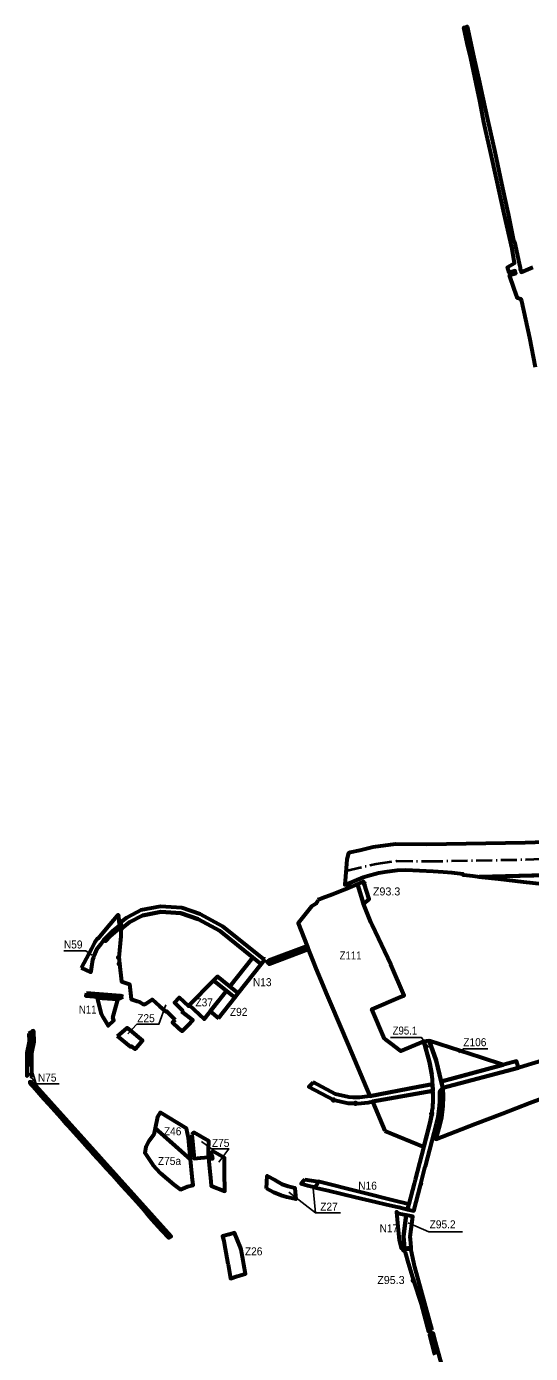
# Model space of a CAD drawing. Extents: x -650277 to -643420, y -1073980 to -1066720.
# Drawn here: x -650277 to -648765, y -1070698 to -1066720 of the extents above; entities that cross this region are included whole.
import ezdxf

# ---------------------------------------------------------------- set-up
doc = ezdxf.new("R2010")
doc.units = 0
doc.header["$LTSCALE"] = 9.6
doc.header["$PDMODE"] = 32
doc.header["$PDSIZE"] = 4.8
doc.linetypes.add('DOT_DASHED', pattern=[7.7, 5, -1.2, 0.3, -1.2])
for name, color, linetype, lineweight in [('1', 7, 'Continuous', 60), ('11', 7, 'Continuous', 60), ('12', 7, 'Continuous', 60), ('13', 7, 'Continuous', 60), ('15', 7, 'Continuous', 60), ('18', 7, 'Continuous', 60), ('24', 7, 'Continuous', 60), ('3', 7, 'Continuous', 60), ('34', 7, 'Continuous', 60), ('40', 7, 'Continuous', 60), ('41', 7, 'Continuous', 60), ('42', 7, 'Continuous', 60), ('48', 7, 'Continuous', 60), ('60', 7, 'Continuous', 60), ('62', 7, 'DOT_DASHED', 40), ('63', 7, 'Continuous', 25), ('7', 7, 'Continuous', 60), ('9', 7, 'Continuous', 60)]:
    doc.layers.add(name, color=color, linetype=linetype, lineweight=lineweight)

msp = doc.modelspace()

# ---------------------------------------------------------------- linework, layer by layer
at = {"layer": '1'}
for points in [[(-650004.59, -1069747.27), (-649974.86, -1069721.96), (-649966.52, -1069728.87), (-649929.38, -1069759.65), (-649951.56, -1069785.42), (-649963, -1069776.7), (-649965, -1069778.7)], [(-649557.21, -1070203.53), (-649555.44, -1070165.91), (-649532.57, -1070178.08), (-649509.72, -1070190.24), (-649492.67, -1070196.34), (-649472.6, -1070201.15), (-649472.43, -1070202.9), (-649469.176, -1070235.365), (-649496, -1070230), (-649513, -1070225), (-649535, -1070216)], [(-649442.63, -1070176.69), (-649402.29, -1070182.92), (-649404.2, -1070187.43), (-649412.2, -1070200.71), (-649433.3, -1070195.89), (-649453.27, -1070190.02), (-649446.19, -1070180.76)], [(-649678.92, -1070395.81), (-649672.83, -1070429.29), (-649672.49, -1070431.16), (-649664.82, -1070473.32), (-649644.74, -1070466.68), (-649640.18, -1070465.2), (-649624.33, -1070460.03), (-649620.17, -1070459.09), (-649624.97, -1070431.24), (-649627.13, -1070419.17), (-649633, -1070386.46), (-649635.52, -1070380.14), (-649653.03, -1070336.2), (-649669.24, -1070341.04), (-649670.28, -1070341.35), (-649689.02, -1070346.94), (-649685.31, -1070360.88), (-649683.08, -1070373.11)]]:
    msp.add_lwpolyline(points, close=True, dxfattribs=at)
at = {"layer": '11'}
msp.add_lwpolyline([(-649788.91, -1069654.4), (-649744.517, -1069695.746), (-649677.124, -1069610.681), (-649715.908, -1069579.804)], close=True, dxfattribs=at)
at = {"layer": '12'}
for points in [[(-649891.21, -1070022.68), (-649832.007, -1070074.751), (-649784.87, -1070116.76), (-649791.31, -1070051.51), (-649797.45, -1070023.77), (-649876.31, -1069975.93), (-649884.59, -1069988.57)], [(-649891.21, -1070022.68), (-649895.45, -1070042.15), (-649910.34, -1070061.29), (-649919.55, -1070079.01), (-649922.3, -1070096.9), (-649898.55, -1070132.9), (-649874.94, -1070157.19), (-649835.28, -1070191.27), (-649815.33, -1070206.63), (-649794.37, -1070197.2), (-649777.29, -1070193.57), (-649779.75, -1070168.69), (-649784.87, -1070116.76)]]:
    msp.add_lwpolyline(points, close=True, dxfattribs=at)
at = {"layer": '13'}
msp.add_line((-649202.375, -1070030.469), (-649085.737, -1070078.201), dxfattribs=at)
for points in [[(-649057.868, -1069910.51), (-649239.635, -1069943.094), (-649202.375, -1070030.469)], [(-649085.737, -1070078.201), (-649066.487, -1070004.267), (-649061.139, -1069979.254), (-649061.138, -1069979.243)]]:
    msp.add_lwpolyline(points, dxfattribs=at)
msp.add_arc((-649347.129, -1069931.193), 290, 350.46253, 4.08974, dxfattribs=at)
msp.add_point((-649061.138, -1069979.243), dxfattribs=at)
at = {"layer": '15'}
msp.add_line((-649057.868, -1069910.51), (-649058.82, -1069890.548), dxfattribs=at)
for points in [[(-648749.97, -1067741.49), (-648767.84, -1067652.98), (-648791.68, -1067543.78), (-648792.97, -1067537.86), (-648804.08, -1067534.88), (-648813.94, -1067506.27), (-648827.86, -1067465.86), (-648809.65, -1067459.77), (-648809.97, -1067458.52), (-648811.21, -1067453.52), (-648811.4, -1067452.79), (-648829.54, -1067458.42), (-648834.01, -1067441.81), (-648812.91, -1067429.16), (-648820.39, -1067386.83), (-648844.16, -1067281.37), (-648845.94, -1067272.85), (-648867.82, -1067176.66), (-648884.26, -1067099.63), (-648899.1, -1067033.34), (-648905.06, -1067006.7), (-648917.76, -1066942.65), (-648924.32, -1066909.55), (-648936.7, -1066852.52), (-648944.75, -1066815.41), (-648955.15, -1066770.11), (-648965.39, -1066723.15), (-648959.88, -1066721.59), (-648954.86, -1066720.16), (-648935.19, -1066812.53), (-648918.27, -1066888.41), (-648914.11, -1066907.05), (-648893.02, -1067002.5), (-648872.31, -1067095.5), (-648851.87, -1067191.04), (-648835.29, -1067268.93), (-648833.66, -1067276.77), (-648816.06, -1067361.71), (-648813.81, -1067365.91), (-648799.58, -1067430.4), (-648796.8, -1067443.1), (-648795.88, -1067447.21), (-648794.7, -1067452.46), (-648793.71, -1067456.88), (-648757.97, -1067441.51)], [(-649561.17, -1069515.83), (-649566.951, -1069515.099), (-649688.625, -1069418.156), (-649755.971, -1069381.179), (-649810.846, -1069362.154), (-649875.434, -1069357.751), (-649934.363, -1069369.537), (-649945.397, -1069375.277), (-649977.239, -1069391.714), (-649994.329, -1069405.451)], [(-649994.293, -1069425.949), (-649968.465, -1069405.189), (-649929.015, -1069384.784), (-649874.391, -1069373.859)], [(-649874.391, -1069373.859), (-649814.067, -1069377.972), (-649762.488, -1069395.854), (-649697.525, -1069431.522), (-649598.004, -1069510.814), (-649572.972, -1069530.758)], [(-649994.329, -1069405.451), (-649994.329, -1069405.451), (-649994.293, -1069425.949), (-649994.293, -1069425.949)], [(-649572.972, -1069530.758), (-649561.91, -1069516.78), (-649561.17, -1069515.83)], [(-650096.627, -1069617.746), (-650099.55, -1069625.53), (-650002.39, -1069633.65)], [(-649987.49, -1069628.6), (-649994.913, -1069626.246), (-650096.627, -1069617.746)], [(-650002.39, -1069633.65), (-650002.65, -1069637.14), (-649987.49, -1069628.6)], [(-649417.234, -1069885.193), (-649418.94, -1069887.36), (-649430.515, -1069898.514), (-649356.458, -1069937.945)], [(-649246.81, -1069926.27), (-649278.492, -1069930.573), (-649296.851, -1069931.092), (-649310.738, -1069929.342), (-649350.222, -1069920.873), (-649417.234, -1069885.193)], [(-649058.82, -1069890.548), (-649101.89, -1069898.73), (-649246.81, -1069926.27)], [(-649356.458, -1069937.945), (-649312.646, -1069947.342), (-649289.95, -1069948.146)], [(-649289.95, -1069948.146), (-649282.437, -1069948.342), (-649251.805, -1069945.276), (-649239.635, -1069943.094), (-649057.868, -1069910.51)]]:
    msp.add_lwpolyline(points, dxfattribs=at)
for points in [[(-650025.31, -1069446.49), (-649998.512, -1069422.926), (-649999.01, -1069415.628), (-650018.873, -1069431.749), (-650043.521, -1069455.69), (-650045.72, -1069459.1), (-650040.012, -1069461.999)], [(-649547.733, -1069530.185), (-649431.761, -1069486.57), (-649435.578, -1069476.772), (-649550.53, -1069519.68), (-649554.83, -1069525), (-649551.32, -1069528.49), (-649549.69, -1069530.14), (-649548.881, -1069530.963)], [(-649677.124, -1069610.681), (-649651.846, -1069630.82), (-649641.978, -1069618.226), (-649667.188, -1069598.14), (-649688.446, -1069581.203), (-649704.646, -1069568.296), (-649715.908, -1069579.804)], [(-648800.85, -1069841.52), (-648806.946, -1069821.79), (-649032.928, -1069882.782), (-649028.017, -1069902.109)]]:
    msp.add_lwpolyline(points, close=True, dxfattribs=at)
for p in [(-649994.329, -1069405.451), (-649994.293, -1069425.949), (-649356.458, -1069937.945), (-649289.95, -1069948.146)]:
    msp.add_point(p, dxfattribs=at)
at = {"layer": '18'}
for points in [[(-649781.53, -1070041.2), (-649774.45, -1070113.92), (-649754.82, -1070111.89), (-649731.12, -1070109.96), (-649730.96, -1070094.91), (-649730.89, -1070088.96), (-649730.6, -1070061.98), (-649774.73, -1070035.58)], [(-649730.57, -1070115.76), (-649730, -1070122.01), (-649726.22, -1070162.75), (-649725.49, -1070170.64), (-649723.17, -1070195.81), (-649682.04, -1070211.58), (-649683.12, -1070154.14), (-649682.98, -1070132.1), (-649683.57, -1070112.05), (-649717.72, -1070091.61), (-649718.71, -1070093.35), (-649724.36, -1070099.03), (-649719.69, -1070108.94), (-649719.24, -1070114.87)]]:
    msp.add_lwpolyline(points, close=True, dxfattribs=at)
at = {"layer": '24'}
for points in [[(-649321.69, -1069307.61), (-649324.3, -1069308.59), (-649359.48, -1069321.82), (-649389.4, -1069333.35), (-649396.52, -1069336.09), (-649403.92, -1069338.26)], [(-649283.702, -1069294.132), (-649284.695, -1069291.033), (-649300.133, -1069297.95), (-649321.69, -1069307.61)], [(-649060.897, -1069861.994), (-649068, -1069825.147), (-649085.41, -1069762.44), (-649085.41, -1069762.44), (-649099.75, -1069768.575), (-649154.76, -1069792.11), (-649184.05, -1069768.45), (-649200.64, -1069756.53), (-649202.99, -1069754.99), (-649241.11, -1069665.9), (-649155.082, -1069629.097), (-649144.57, -1069624.6), (-649184.1, -1069532.2), (-649240.202, -1069414.528), (-649244.08, -1069404.753), (-649265.774, -1069350.068), (-649283.702, -1069294.132)], [(-649403.92, -1069338.26), (-649403.03, -1069340.66), (-649408.81, -1069349.89), (-649422.19, -1069357.99), (-649462.25, -1069408.32), (-649435.578, -1069476.772), (-649431.761, -1069486.57)], [(-649431.761, -1069486.57), (-649416.52, -1069525.68), (-649409.355, -1069544.517), (-649388.438, -1069594.296), (-649379.32, -1069615.71), (-649364.44, -1069650.55), (-649312.03, -1069773.33)], [(-649312.03, -1069773.33), (-649246.81, -1069926.27), (-649101.89, -1069898.73), (-649058.82, -1069890.548)]]:
    msp.add_lwpolyline(points, dxfattribs=at)
msp.add_arc((-649649.71, -1069919.176), 591.583, 2.77379, 5.54687, dxfattribs=at)
at = {"layer": '3'}
msp.add_lwpolyline([(-648722.24, -1069817.54), (-648772.48, -1069832.83), (-648800.85, -1069841.52), (-649028.017, -1069902.109), (-649027.135, -1069928.902), (-649027.953, -1069955.702), (-649032.644, -1069990.371), (-649037.411, -1070011.659), (-649048.918, -1070055.852), (-648931.057, -1070010.171), (-648849.532, -1069978.559), (-648767.83, -1069946.87), (-648562.242, -1069870.301)], dxfattribs=at)
at = {"layer": '34'}
msp.add_line((-649032.928, -1069882.782), (-649002.558, -1069874.585), dxfattribs=at)
for points in [[(-649002.558, -1069874.585), (-648846.924, -1069832.58), (-648914.48, -1069810.75), (-649069.4, -1069760.67)], [(-649069.4, -1069760.67), (-649048, -1069820), (-649032.928, -1069882.782)]]:
    msp.add_lwpolyline(points, dxfattribs=at)
at = {"layer": '40'}
for points in [[(-649667.188, -1069598.14), (-649641.978, -1069618.226), (-649572.972, -1069530.758), (-649598.004, -1069510.814)], [(-650002.65, -1069637.14), (-650050.26, -1069633.65), (-650064.77, -1069633.06), (-650052.88, -1069679.49), (-650047.45, -1069690.69), (-650031.64, -1069715.9), (-650015.53, -1069700.21), (-650018.31, -1069690.89), (-650011.15, -1069665.82)], [(-649160.748, -1070243.413), (-649402.29, -1070182.92), (-649404.2, -1070187.43), (-649412.2, -1070200.71), (-649412.2, -1070200.71), (-649408.24, -1070201.62), (-649372.69, -1070209.74), (-649289.83, -1070229.16), (-649229.8, -1070243.94), (-649197.55, -1070251.65), (-649164.91, -1070258.55), (-649160.54, -1070259.96), (-649134.294, -1070266.095), (-649130.712, -1070250.935)]]:
    msp.add_lwpolyline(points, close=True, dxfattribs=at)
at = {"layer": '41'}
msp.add_line((-650000.59, -1069511.15), (-649998.5, -1069529.88), dxfattribs=at)
for points in [[(-649814.067, -1069377.972), (-649874.391, -1069373.859), (-649929.015, -1069384.784), (-649968.465, -1069405.189)], [(-649598.004, -1069510.814), (-649697.525, -1069431.522), (-649762.488, -1069395.854), (-649814.067, -1069377.972)], [(-649968.465, -1069405.189), (-649994.293, -1069425.949), (-649994.53, -1069447.61), (-650000.59, -1069511.15), (-650000.59, -1069511.15)], [(-649998.5, -1069529.88), (-649992.59, -1069582.88), (-649967.81, -1069590.74), (-649962.71, -1069636.458)], [(-649812.153, -1069672.884), (-649809.47, -1069670.13), (-649833.38, -1069646.08), (-649818.71, -1069630.64), (-649791.3, -1069657.21), (-649788.91, -1069654.4), (-649715.908, -1069579.804), (-649704.646, -1069568.296), (-649688.446, -1069581.203), (-649667.188, -1069598.14), (-649598.004, -1069510.814)], [(-649962.71, -1069636.458), (-649962.71, -1069636.46), (-649954.365, -1069639.105), (-649944.963, -1069642.085)], [(-649944.963, -1069642.085), (-649938.2, -1069644.23), (-649924.8, -1069652.19), (-649920.45, -1069649.53), (-649900.64, -1069636.78), (-649877.82, -1069656.83), (-649864.596, -1069668.455), (-649859.96, -1069672.53)], [(-649859.96, -1069672.53), (-649859.17, -1069673.22), (-649857.49, -1069671.46), (-649833.94, -1069695.24), (-649831.124, -1069698.083)], [(-649812.153, -1069672.884), (-649808.96, -1069675.34), (-649777.94, -1069699.2), (-649792.13, -1069713.65), (-649807.66, -1069729.46), (-649810.41, -1069732.28), (-649819.9, -1069723.61), (-649838.99, -1069706.15), (-649831.124, -1069698.083)], [(-649831.124, -1069698.083), (-649838.99, -1069706.15), (-649819.9, -1069723.61), (-649810.41, -1069732.28), (-649807.66, -1069729.46), (-649792.13, -1069713.65), (-649777.94, -1069699.2), (-649808.96, -1069675.34), (-649812.153, -1069672.884)]]:
    msp.add_lwpolyline(points, dxfattribs=at)
for p in [(-650000.59, -1069511.15), (-649998.5, -1069529.88)]:
    msp.add_point(p, dxfattribs=at)
at = {"layer": '42'}
msp.add_lwpolyline([(-650112.18, -1069542.11), (-650081.29, -1069484.35), (-650072.5, -1069466.44), (-650063.12, -1069453.54), (-650062.17, -1069454.05), (-650060.29, -1069451.7), (-650057.49, -1069448.18), (-650026.33, -1069411.47), (-650003.73, -1069384.71), (-650002.11, -1069382.8), (-650001.13, -1069388.13), (-649999.95, -1069397.98), (-649999.01, -1069415.628), (-650018.873, -1069431.749), (-650043.521, -1069455.69), (-650045.72, -1069459.1), (-650055.612, -1069471.639), (-650066.897, -1069487.541), (-650069.369, -1069492.132), (-650074.75, -1069506.133), (-650076.365, -1069510.333), (-650079.264, -1069517.874), (-650080.302, -1069525.418), (-650080.802, -1069530.768), (-650082.963, -1069544.736), (-650084.345, -1069554.773)], close=True, dxfattribs=at)
at = {"layer": '48'}
for points in [[(-650270.059, -1069739.232), (-650269.449, -1069762.714), (-650276.214, -1069796.532), (-650275.76, -1069865.474), (-650274.95, -1069865.62), (-650273.87, -1069809.74), (-650273.78, -1069805.2), (-650273.58, -1069794.48), (-650270.15, -1069778.65), (-650267.22, -1069765.1), (-650265.37, -1069741.61), (-650264.91, -1069735.69)], [(-650260.645, -1069868.536), (-650260.748, -1069867.327), (-650261.204, -1069797.969), (-650254.411, -1069764.006), (-650255.21, -1069733.253), (-650255.716, -1069731.162), (-650259.97, -1069732.29), (-650258.74, -1069750.62), (-650257.77, -1069765.2), (-650262.93, -1069794.84), (-650262.77, -1069805.54), (-650262.7, -1069809.89), (-650261.8, -1069868.33)], [(-650257.713, -1069885.547), (-650266.89, -1069883.7), (-650266.68, -1069886.78), (-650262.64, -1069891.57), (-650257.16, -1069898.07), (-650224.71, -1069934.41), (-650209.51, -1069951.43), (-650192.51, -1069970.47), (-650174.3, -1069990.86), (-650157.87, -1070009.26), (-650151.03, -1070016.84), (-650134.26, -1070035.45), (-650106.76, -1070065.96), (-650091.89, -1070082.46), (-650087.18, -1070087.68), (-650076.72, -1070099.29), (-650051.33, -1070127.45), (-650037.78, -1070142.48), (-650018.41, -1070163.97), (-650005.3, -1070178.51), (-649990.95, -1070194.43), (-649977.05, -1070209.85), (-649946.39, -1070243.87), (-649930.46, -1070261.54), (-649924.15, -1070268.55), (-649913.03, -1070282.44), (-649901.59, -1070296.73), (-649871.28, -1070329.01), (-649850.04, -1070351.64), (-649843.513, -1070347.685)]]:
    msp.add_lwpolyline(points, close=True, dxfattribs=at)
at = {"layer": '60'}
for p, q in [((-649058.858, -1069889.759), (-649057.868, -1069910.51)), ((-649057.134, -1069932.873), (-649057.868, -1069910.51)), ((-649146.163, -1070347.543), (-649145.424, -1070357.637))]:
    msp.add_line(p, q, dxfattribs=at)
for points in [[(-648721.315, -1069164.952), (-648781.015, -1069167.44), (-649076.02, -1069172.683), (-649169.781, -1069171.432), (-649237.512, -1069180.731), (-649277.021, -1069189.913), (-649306.455, -1069196.754), (-649311.633, -1069197.958), (-649316.47, -1069216.91), (-649321.32, -1069281.47), (-649322.09, -1069291.73), (-649322.22, -1069293.54), (-649319.72, -1069292.47), (-649267.5, -1069270.41), (-649242.5, -1069263.3), (-649220.18, -1069257.03), (-649202.63, -1069254.4), (-649165.62, -1069249.43), (-649139.63, -1069248.73), (-649056.95, -1069252.55), (-649026.955, -1069254.366), (-649001.3, -1069255.92), (-648968.49, -1069260.36), (-648968.05, -1069263.06), (-648965.8, -1069262.75), (-648937.91, -1069266.51), (-648924.13, -1069268.21), (-648918.889, -1069268.875), (-648673.267, -1069262.895)], [(-649061.138, -1069979.243), (-649061.138, -1069979.243), (-649061.139, -1069979.254), (-649066.487, -1070004.267), (-649098.65, -1070127.795), (-649110.925, -1070177.113), (-649114.174, -1070189.816), (-649130.712, -1070250.935), (-649134.294, -1070266.095), (-649115.159, -1070270.568), (-649095.152, -1070193.731), (-649093.095, -1070186.132), (-649095.152, -1070193.731), (-649080.924, -1070137.409), (-649080.38, -1070136.996), (-649047.131, -1070009.304), (-649042.468, -1069988.477), (-649042.468, -1069988.477), (-649039.966, -1069973.035), (-649037.98, -1069956.626), (-649037.322, -1069942.129), (-649037.137, -1069928.996), (-649037.665, -1069912.977), (-649028.017, -1069902.109), (-649032.928, -1069882.782), (-649048, -1069820), (-649069.4, -1069760.67), (-649085.41, -1069762.44), (-649068, -1069825.147), (-649060.897, -1069861.994)], [(-649138.43, -1070283.6), (-649146.163, -1070347.543), (-649146.163, -1070347.543)], [(-649125.503, -1070355.837), (-649126.069, -1070348.097), (-649118.257, -1070287.455), (-649138.43, -1070283.6)], [(-649145.424, -1070357.637), (-649143.633, -1070382.123), (-649123.693, -1070380.572), (-649125.503, -1070355.837)], [(-649059.951, -1070628.223), (-649112.14, -1070439.152), (-649123.138, -1070388.16), (-649123.385, -1070384.775), (-649145.73, -1070387.91)], [(-649145.73, -1070387.91), (-649141.48, -1070394.84), (-649132.07, -1070426.81), (-649116.56, -1070479.19)], [(-649116.56, -1070479.19), (-649093.2, -1070549.1), (-649071.33, -1070632.6), (-649059.951, -1070628.223)], [(-649025.129, -1070754.377), (-649047.11, -1070674.743), (-649050.081, -1070663.981), (-649057.338, -1070637.689), (-649068.65, -1070642.23), (-649068.65, -1070642.23), (-649054.31, -1070696.44), (-649052.77, -1070702.25)]]:
    msp.add_lwpolyline(points, dxfattribs=at)
for points in [[(-648730.66, -1069290.43), (-648656.242, -1069297.116), (-648673.267, -1069262.895), (-648761.189, -1069265.035), (-648918.889, -1069268.875), (-648909.86, -1069270.02), (-648861.49, -1069275.34), (-648785.92, -1069284.2), (-648730.66, -1069290.43)], [(-649701.211, -1069692.826), (-649651.773, -1069630.879), (-649677.124, -1069610.681), (-649726.033, -1069672.415)]]:
    msp.add_lwpolyline(points, close=True, dxfattribs=at)
for centre, radius, start, end in [((-649633.43, -1069918.001), 575.266, 2.81398, 5.58706), ((-649347.129, -1069931.193), 290, 350.46253, 4.08974), ((-649347.129, -1069931.193), 290, 359.66809, 4.08974)]:
    msp.add_arc(centre, radius, start, end, dxfattribs=at)
for p in [(-649145.73, -1070387.91), (-649116.56, -1070479.19)]:
    msp.add_point(p, dxfattribs=at)
at = {"layer": '62'}
msp.add_lwpolyline([(-649319.032, -1069251.01), (-649228.433, -1069229.954), (-649166.697, -1069221.478), (-649075.909, -1069222.689), (-648779.53, -1069217.422), (-648667.088, -1069212.737)], dxfattribs=at)
at = {"layer": '63'}
for p, q in [((-650248, -1069890), (-650277, -1069850)), ((-650248, -1069890), (-650261, -1069847)), ((-649410, -1070277), (-649417.769, -1070193.978))]:
    msp.add_line(p, q, dxfattribs=at)
for points in [[(-650165, -1069491), (-650099, -1069491), (-650081, -1069504)], [(-649973, -1069740), (-649946, -1069711), (-649880, -1069711), (-649859, -1069653)], [(-649185, -1069751), (-649092, -1069751), (-649071, -1069781)], [(-648893, -1069785), (-648967, -1069785), (-648980, -1069797)], [(-650243, -1069909), (-650248, -1069890), (-650179, -1069890)], [(-649752, -1070063), (-649722, -1070085), (-649670, -1070085), (-649700, -1070125)], [(-649335, -1070277), (-649410, -1070277), (-649490, -1070215)], [(-648969, -1070333), (-649070, -1070333), (-649132, -1070306)]]:
    msp.add_lwpolyline(points, dxfattribs=at)
at = {"layer": '7'}
msp.add_lwpolyline([(-649138.43, -1070283.6), (-649159.78, -1070279.52), (-649166.86, -1070273.48), (-649162.91, -1070317.47), (-649159.19, -1070358.82), (-649153.64, -1070382.9), (-649148.23, -1070382.48), (-649143.633, -1070382.123), (-649146.163, -1070347.543)], close=True, dxfattribs=at)
at = {"layer": '9'}
msp.add_line((-649283.702, -1069294.132), (-649265.774, -1069350.068), dxfattribs=at)
for points in [[(-649264.156, -1069289.589), (-649266.331, -1069282.804), (-649284.695, -1069291.033), (-649283.702, -1069294.132)], [(-649265.774, -1069350.068), (-649249.069, -1069336.66), (-649264.156, -1069289.589)]]:
    msp.add_lwpolyline(points, dxfattribs=at)
for p in [(-649283.702, -1069294.132), (-649264.156, -1069289.589)]:
    msp.add_point(p, dxfattribs=at)

# ---------------------------------------------------------------- texts
at = {"layer": '63'}
for s, p in [('Z93.3', (-649238, -1069325)), ('Z95.3', (-649225, -1070490))]:
    msp.add_text(s, height=24, dxfattribs=at).set_placement(p)
for s, width, p in [('N59', 0.95, (-650165, -1069484)), ('Z111', 0.9, (-649338, -1069517)), ('N13', 0.95, (-649598, -1069597)), ('N11', 0.9, (-650120, -1069679)), ('Z37', 0.95, (-649770.387, -1069657.603)), ('Z92', 0.95, (-649667, -1069686)), ('Z25', 0.95, (-649945, -1069705)), ('Z95.1', 0.9, (-649179, -1069742)), ('Z106', 0.95, (-648967, -1069777)), ('N75', 0.95, (-650243, -1069883)), ('Z46', 0.95, (-649865, -1070044)), ('Z75', 0.95, (-649721, -1070079)), ('Z75a', 0.95, (-649883, -1070133)), ('N16', 0.95, (-649282, -1070207)), ('Z27', 0.95, (-649396, -1070270)), ('Z95.2', 0.95, (-649068, -1070323)), ('N17', 0.95, (-649218, -1070335)), ('Z26', 0.95, (-649622, -1070404))]:
    msp.add_text(s, height=24, dxfattribs=dict(at, width=width)).set_placement(p)

doc.saveas('drawing.dxf')
